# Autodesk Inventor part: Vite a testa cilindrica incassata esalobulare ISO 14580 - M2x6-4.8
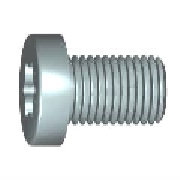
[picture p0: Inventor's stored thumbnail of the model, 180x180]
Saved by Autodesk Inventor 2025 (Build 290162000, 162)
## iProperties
Created: 2024-01
Part Number: Vite a testa cilindrica incassata esalobulare ISO 14580 - M2x6-4.8
Material: Acciaio
Description: ISO 14580 - Viti a testa cilindrica incassata esalobulare - Seconda edizione
Document SubType Name: Modeling
Standard: 14580
Designer: Ryzen5700u
Standards Organization: ISO
Language: it-IT
Size Designation: M2x6-4.8
Categories: <MemberInstance><Categories><Category DisplayName="Elementi di fissaggio" InternalName="e4da775c-781d-43d5-af7c-5136215cf5a6" Mnemonic="FSTN"><Category DisplayN
Density: 7.85 g/cm^3
Appearance: Lamiera
IsCustomPart: 0
Author: Ryzen5700u
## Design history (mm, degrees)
revolve "Revolution1" stored, may be unused: angle "d4" = 90 deg
thread "Thread1" dims "d6" = 6 (= b), "d7" = 0
sketch "Sketch2" dims "d21" = 1.75 (= A_)
  geometry: L1 (-0.53, -0.306)-(-0.875, 0); L2 (0, 0)-(-0.53, -0.306); L3 (0, 0)-(-0.53, 0.306); L4 (-2.85, 0)-(2.85, 0) reference; L5 (-0.875, 0)-(-0.53, 0.306); A1 r 0.613 centre (0, 0) between (-0.53, -0.306) and (-0.53, 0.306); 2 further points
  constraints: 8 end point, 2 coincident, 2 point on circle, 1 centre point, 1 horizontal alignment, 1 point on line, 2 other
  dimensions: "d19" = 60 deg angle of L3 L2; "d20" = 30 deg angle of L3 L4 (= 0.5 x d19); "d26" = 1.225 diameter of A1 (= 0.7 x d21)
extrude "Extrusion1" cut sketch "Sketch2" distance "d27" = 0.84 (= t); taper "d28" = 0 deg
pattern_circular "Circular Pattern1" dims angle "d30" = 360 deg
fillet "Fillet2" dims "d32" = 0.2 (= v)
fillet "Fillet3" dims "d33" = 0.2 (= v)
fillet "Fillet5" dims "d35" = 0.1 (= r)
chamfer "Chamfer2" distance "d36" = 0.2 (= v); stored, may be unused: second distance "d37" = 2, angle "d38" = 45 deg
body "Solid1"
sketch "Sketch1"
  geometry: L1 (0, 0)-(6, 0); L2 (6, 0)-(6, 1); L3 (6, 1)-(0, 1); L4 (0, 1)-(0, 0); L5 (0, 0)-(-1.55, 0); L6 (-1.55, 0)-(-1.55, 1.9); L7 (-1.55, 1.9)-(0, 2.036); L8 (0, 2.036)-(0, 0)
  constraints: 16 end point, 3 parallel, 2 horizontal, 2 perpendicular
  dimensions: "d0" = 2 diameter of L3 L1 (= d); "d3" = 6 distance of L2.end L3.end (= l_); "d46" = 85 deg angle of L8 L7; "d47" = 1.55 distance between parallel lines of L8 L6 (= k); "d49" = 3.8 diameter of L6.end L1 (= dk)
other parameters: "A_" = 1.75 [user parameter; used in 1 equation term], "d" = 2 [user parameter; used in 2 equation terms], "dk" = 3.8 [user parameter; used in 1 equation term], "k" = 1.55 [user parameter; used in 1 equation term], "l_" = 6 [user parameter; used in 2 equation terms], "lg" = 0 [user parameter; used in 1 equation term], "t" = 0.84 [user parameter; used in 1 equation term], "w" = 0.55 [user parameter], "v" = 0.2 [user parameter; used in 3 equation terms], "r" = 0.1 [user parameter; used in 1 equation term], "da" = 2.6 [user parameter], "ds_" = 2 (= d) [user parameter], "ls" = 0 [user parameter], "b" = 6 (= l_ - lg) [user parameter; used in 1 equation term], "d42" = 0, "d43" = 0, "d44" = 0, "p" = 0.4 [user parameter]
